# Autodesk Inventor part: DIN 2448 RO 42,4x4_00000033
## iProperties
Created: 2006-02
Part Number: DIN 2448 RO 42,4x4_00000033
Material: Default
Document SubType Name: Modeling
Designer: FranzK
Stock Number: DIN 2448 RO 42,4x4
Mass: 1645.49 g
Surface Area: 8237.11 cm^2
Volume: 1645.49 cm^3
Density: 1 g/cm^3
G_L: 3410.000 mm
G_W: 42.400 mm
G_H: 42.400 mm
AFG_Item: 42.4 x 4
CSToolsMass: 2.0
CSToolsVolume: 1645491.0
CSToolsArea: 8237.0
Author: FranzK
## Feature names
1. AFG_Detailed_DIN 2448 RO 42,4x4_00000033 [Extrusion]
2. AFG_Simplified_DIN 2448 RO 42,4x4_00000033 [Extrusion]
